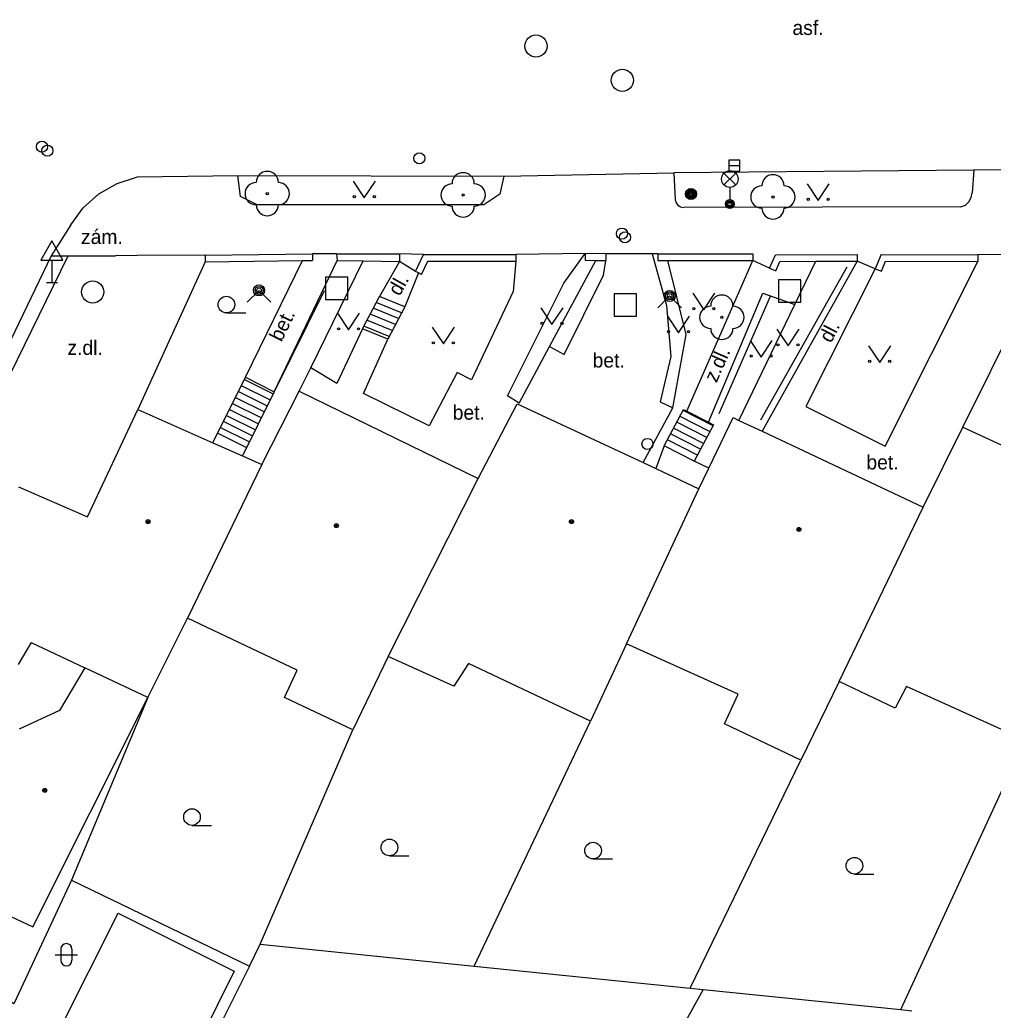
# Model space of a CAD drawing. Extents: x -600309 to -598967, y -1161267 to -1160292.
# Drawn here: x -599981.24 to -599937.41, y -1160664.81 to -1160620.23 of the extents above; entities that cross this region are included whole.
import ezdxf

# ---------------------------------------------------------------- set-up
doc = ezdxf.new("R2010")
doc.units = 0
for name, color, linetype in [('Level 10', 7, 'Continuous'), ('Level 11', 7, 'Continuous'), ('Level 22', 7, 'Continuous'), ('Level 25', 7, 'Continuous'), ('Level 26', 7, 'Continuous'), ('Level 27', 7, 'Continuous'), ('Level 28', 7, 'Continuous'), ('Level 31', 7, 'Continuous'), ('Level 33', 7, 'Continuous'), ('Level 34', 7, 'Continuous'), ('Level 36', 7, 'Continuous'), ('Level 39', 7, 'Continuous'), ('Level 40', 7, 'Continuous'), ('Level 5', 7, 'Continuous'), ('Level 51', 7, 'Continuous'), ('Level 7', 7, 'Continuous'), ('Level 8', 7, 'Continuous')]:
    doc.layers.add(name, color=color, linetype=linetype)

msp = doc.modelspace()

# ---------------------------------------------------------------- linework, layer by layer
at = {"layer": 'Level 10'}
for points in [[(-599959.45, -1160627.26), (-599951.79, -1160627.11)], [(-599938.28, -1160627), (-599951.79, -1160627.11)], [(-599930.96, -1160626.92), (-599938.28, -1160627)], [(-599978.95, -1160629.46), (-599978.39, -1160628.69), (-599977.68, -1160628.06), (-599976.86, -1160627.59), (-599975.95, -1160627.3)], [(-599975.95, -1160627.3), (-599971.43, -1160627.24)], [(-599971.43, -1160627.24), (-599959.45, -1160627.26)], [(-599978.95, -1160629.46), (-599979.83, -1160630.85)], [(-599979.83, -1160630.85), (-599983.85, -1160639.19), (-599988.07, -1160648)]]:
    msp.add_lwpolyline(points, dxfattribs=at)
at = {"layer": 'Level 11'}
for points in [[(-599951.79, -1160627.11), (-599951.73, -1160628.33)], [(-599938.28, -1160627), (-599938.36, -1160628.02)], [(-599959.45, -1160627.26), (-599959.63, -1160628.07), (-599960.35, -1160628.55), (-599970.55, -1160628.55), (-599970.97, -1160628.34), (-599971.3, -1160628.18), (-599971.43, -1160627.24)], [(-599938.86, -1160628.65), (-599938.6599, -1160628.57), (-599938.5, -1160628.42), (-599938.4, -1160628.23), (-599938.36, -1160628.02)], [(-599951.73, -1160628.33), (-599951.69, -1160628.46), (-599951.61, -1160628.57), (-599951.49, -1160628.65), (-599951.36, -1160628.68)], [(-599938.86, -1160628.65), (-599951.36, -1160628.68)], [(-599979.83, -1160630.85), (-599979.06, -1160630.85)], [(-599972.9, -1160631.12), (-599975.93, -1160637.77)], [(-599971.08, -1160636.32), (-599968.51, -1160631.07)], [(-599969.79, -1160636.98), (-599966.96, -1160631.06)], [(-599968.66, -1160636.95), (-599968.14, -1160635.89), (-599965.78, -1160631.08)], [(-599958.91, -1160631.09), (-599959.02, -1160632.46), (-599960.9, -1160636.44), (-599961.55, -1160636.11), (-599962.81, -1160638.5), (-599965.76, -1160637.05), (-599964.67, -1160634.61)], [(-599964.15, -1160631.11), (-599965.05, -1160632.68)], [(-599963.06, -1160630.8), (-599964.15, -1160630.77)], [(-599958.76, -1160637.49), (-599959.28, -1160637.15), (-599956.75, -1160632.09), (-599955.78, -1160630.75)], [(-599957.39, -1160634.94), (-599956.73, -1160635.29), (-599954.96, -1160631.72), (-599954.86, -1160631.07)], [(-599953.18, -1160640.16), (-599951.84, -1160637.69), (-599951.24, -1160634.4), (-599952.06, -1160631.06)], [(-599952.77, -1160630.76), (-599952.12, -1160633.09), (-599951.93, -1160635.39), (-599952.41, -1160637.42), (-599951.84, -1160637.69)], [(-599951.21, -1160637.84), (-599948.23, -1160631.07)], [(-599943.54, -1160631.09), (-599947.82, -1160638.75)], [(-599942.72, -1160631.44), (-599945.85, -1160637.63), (-599942.28, -1160639.42), (-599938.1, -1160631.11)], [(-599963.29, -1160631.62), (-599963.91, -1160633.15)], [(-599965.81, -1160634.14), (-599965.05, -1160632.68)], [(-599963.91, -1160633.15), (-599965.05, -1160632.68)], [(-599950.23, -1160638.34), (-599947.79, -1160632.53), (-599946.34, -1160633.05)], [(-599964.19, -1160633.68), (-599965.33, -1160633.21)], [(-599964.05, -1160633.42), (-599965.19, -1160632.95)], [(-599963.91, -1160633.15), (-599964.67, -1160634.61)], [(-599964.47, -1160634.22), (-599965.61, -1160633.75)], [(-599964.33, -1160633.95), (-599965.47, -1160633.48)], [(-599965.81, -1160634.14), (-599966.97, -1160636.6), (-599968.14, -1160635.89)], [(-599964.67, -1160634.61), (-599965.81, -1160634.14)], [(-599964.61, -1160634.49), (-599965.75, -1160634.02)], [(-599972.55, -1160639.27), (-599971.08, -1160636.32)], [(-599971.13, -1160636.42), (-599969.83, -1160637.06)], [(-599971.08, -1160636.32), (-599969.79, -1160636.98)], [(-599971.27, -1160636.69), (-599969.97, -1160637.33)], [(-599971.53, -1160637.23), (-599970.23, -1160637.87)], [(-599971.4, -1160636.96), (-599970.1, -1160637.6)], [(-599969.79, -1160636.98), (-599971.22, -1160639.86)], [(-599971.8, -1160637.77), (-599970.5, -1160638.41)], [(-599971.66, -1160637.5), (-599970.36, -1160638.14)], [(-599952.22, -1160639.4), (-599951.35, -1160637.77), (-599951.21, -1160637.84), (-599950.23, -1160638.34), (-599950, -1160638.46), (-599950.87, -1160640.09)], [(-599950.02, -1160638.5), (-599951.37, -1160637.81)], [(-599971.93, -1160638.04), (-599970.63, -1160638.68)], [(-599950.16, -1160638.77), (-599951.51, -1160638.08)], [(-599972.2, -1160638.58), (-599970.9, -1160639.22)], [(-599972.06, -1160638.31), (-599970.76, -1160638.95)], [(-599950.45, -1160639.3), (-599951.8, -1160638.61)], [(-599950.3, -1160639.03), (-599951.65, -1160638.34)], [(-599972.33, -1160638.84), (-599971.03, -1160639.48)], [(-599950.73, -1160639.82), (-599952.08, -1160639.13)], [(-599950.59, -1160639.56), (-599951.94, -1160638.87)], [(-599952.22, -1160639.4), (-599952.61, -1160640.43)], [(-599950.87, -1160640.09), (-599952.22, -1160639.4)], [(-599950.21, -1160640.41), (-599950.87, -1160640.09)]]:
    msp.add_lwpolyline(points, dxfattribs=at)
at = {"layer": 'Level 22'}
for centre in [(-599970.1, -1160628.05), (-599961.28, -1160628.11), (-599947.33, -1160628.2), (-599949.63, -1160633.62)]:
    msp.add_circle(centre, 0.05, dxfattribs=at)
for centre, start, end in [((-599970.1, -1160627.55), 0, 180), ((-599961.28, -1160627.61), 0, 180), ((-599970.6, -1160628.05), 90, 270), ((-599969.6, -1160628.05), 270, 90), ((-599947.33, -1160627.7), 0, 180), ((-599961.78, -1160628.11), 90, 270), ((-599960.78, -1160628.11), 270, 90), ((-599947.83, -1160628.2), 90, 270), ((-599946.83, -1160628.2), 270, 90), ((-599970.1, -1160628.55), 180, 0), ((-599961.28, -1160628.61), 180, 0), ((-599947.33, -1160628.7), 180, 0), ((-599949.63, -1160633.12), 0, 180), ((-599950.13, -1160633.62), 90, 270), ((-599949.13, -1160633.62), 270, 90), ((-599949.63, -1160634.12), 180, 0)]:
    msp.add_arc(centre, 0.5, start, end, dxfattribs=at)
at = {"layer": 'Level 25'}
for radius in [0.25, 0.2, 0.15, 0.1, 0.05]:
    msp.add_circle((-599951.02, -1160628.07), radius, dxfattribs=at)
at = {"layer": 'Level 26'}
for points in [[(-599967.48, -1160632.82), (-599966.48, -1160632.82), (-599966.48, -1160631.82), (-599967.48, -1160631.82)], [(-599947.08, -1160632.94), (-599946.08, -1160632.94), (-599946.08, -1160631.94), (-599947.08, -1160631.94)], [(-599954.48, -1160633.57), (-599953.48, -1160633.57), (-599953.48, -1160632.57), (-599954.48, -1160632.57)]]:
    msp.add_lwpolyline(points, close=True, dxfattribs=at)
at = {"layer": 'Level 27'}
msp.add_line((-599949.32, -1160626.79), (-599948.82, -1160626.79), dxfattribs=at)
msp.add_lwpolyline([(-599949.32, -1160627.04), (-599948.82, -1160627.04), (-599948.82, -1160626.54), (-599949.32, -1160626.54)], close=True, dxfattribs=at)
for centre in [(-599958, -1160621.41), (-599954.11, -1160622.95), (-599977.96, -1160632.48)]:
    msp.add_circle(centre, 0.5, dxfattribs=at)
at = {"layer": 'Level 28'}
for centre in [(-599980.25, -1160625.94), (-599980, -1160626.12), (-599963.25, -1160626.46), (-599954.13, -1160629.85), (-599953.99, -1160630.02)]:
    msp.add_circle(centre, 0.25, dxfattribs=at)
at = {"layer": 'Level 31'}
for points in [[(-599971, -1160632.94), (-599970.47, -1160632.41), (-599969.94, -1160632.94)], [(-599952.51, -1160633.19), (-599951.98, -1160632.66), (-599951.45, -1160633.19)]]:
    msp.add_lwpolyline(points, dxfattribs=at)
for centre, radius in [((-599970.47, -1160632.41), 0.25), ((-599970.47, -1160632.41), 0.18), ((-599970.47, -1160632.41), 0.11), ((-599951.98, -1160632.66), 0.25), ((-599951.98, -1160632.66), 0.18), ((-599951.98, -1160632.66), 0.11), ((-599952.98, -1160639.32), 0.25)]:
    msp.add_circle(centre, radius, dxfattribs=at)
at = {"layer": 'Level 33'}
for p, q in [((-599949.535, -1160627.66), (-599949.005, -1160627.13)), ((-599949.535, -1160627.13), (-599949.005, -1160627.66)), ((-599949.27, -1160627.77), (-599949.27, -1160628.52))]:
    msp.add_line(p, q, dxfattribs=at)
for centre, radius in [((-599949.27, -1160627.395), 0.375), ((-599949.27, -1160628.52), 0.2), ((-599949.27, -1160628.52), 0.1445), ((-599949.27, -1160628.52), 0.0876)]:
    msp.add_circle(centre, radius, dxfattribs=at)
at = {"layer": 'Level 34'}
for p, q in [((-599979.8, -1160631.042), (-599979.8, -1160632.06)), ((-599980.05, -1160632.06), (-599979.55, -1160632.06))]:
    msp.add_line(p, q, dxfattribs=at)
msp.add_lwpolyline([(-599980.3, -1160631.042), (-599979.3, -1160631.042), (-599979.8, -1160630.176)], close=True, dxfattribs=at)
at = {"layer": 'Level 36'}
for p, q in [((-599971.94, -1160633.425), (-599971.065, -1160633.425)), ((-599973.49, -1160656.495), (-599972.615, -1160656.495)), ((-599964.6, -1160657.865), (-599963.725, -1160657.865)), ((-599955.43, -1160658.005), (-599954.555, -1160658.005)), ((-599943.6599, -1160658.685), (-599942.7849, -1160658.685)), ((-599979.646, -1160662.316), (-599978.646, -1160662.316)), ((-599979.396, -1160662.066), (-599979.396, -1160662.566)), ((-599978.896, -1160662.066), (-599978.896, -1160662.566))]:
    msp.add_line(p, q, dxfattribs=at)
for points in [[(-599966.23, -1160627.49), (-599965.73, -1160628.24), (-599965.23, -1160627.49)], [(-599945.79, -1160627.61), (-599945.29, -1160628.36), (-599944.79, -1160627.61)], [(-599950.94, -1160632.53), (-599950.44, -1160633.28), (-599949.94, -1160632.53)], [(-599957.78, -1160633.19), (-599957.28, -1160633.94), (-599956.78, -1160633.19)], [(-599966.94, -1160633.44), (-599966.44, -1160634.19), (-599965.94, -1160633.44)], [(-599952.08, -1160633.57), (-599951.58, -1160634.32), (-599951.08, -1160633.57)], [(-599962.67, -1160634.07), (-599962.17, -1160634.82), (-599961.67, -1160634.07)], [(-599947.15, -1160634.16), (-599946.65, -1160634.91), (-599946.15, -1160634.16)], [(-599948.36, -1160634.66), (-599947.86, -1160635.41), (-599947.36, -1160634.66)], [(-599943.02, -1160634.9), (-599942.52, -1160635.65), (-599942.02, -1160634.9)]]:
    msp.add_lwpolyline(points, dxfattribs=at)
for centre, radius in [((-599966.1802, -1160628.1898), 0.05), ((-599965.2808, -1160628.1898), 0.05), ((-599945.7402, -1160628.3098), 0.05), ((-599944.8408, -1160628.3098), 0.05), ((-599971.9401, -1160633.0499), 0.375), ((-599950.8902, -1160633.2298), 0.05), ((-599949.9908, -1160633.2298), 0.05), ((-599966.8902, -1160634.1398), 0.05), ((-599965.9908, -1160634.1398), 0.05), ((-599957.7302, -1160633.8898), 0.05), ((-599956.8308, -1160633.8898), 0.05), ((-599952.0302, -1160634.2698), 0.05), ((-599951.1308, -1160634.2698), 0.05), ((-599962.6202, -1160634.7698), 0.05), ((-599961.7208, -1160634.7698), 0.05), ((-599947.1002, -1160634.8598), 0.05), ((-599946.2008, -1160634.8598), 0.05), ((-599948.3102, -1160635.3598), 0.05), ((-599947.4108, -1160635.3598), 0.05), ((-599942.9702, -1160635.5998), 0.05), ((-599942.0708, -1160635.5998), 0.05), ((-599973.4901, -1160656.1199), 0.375), ((-599964.6001, -1160657.4899), 0.375), ((-599955.4301, -1160657.6299), 0.375), ((-599943.66, -1160658.3099), 0.375)]:
    msp.add_circle(centre, radius, dxfattribs=at)
for centre, start, end in [((-599979.1457, -1160662.0663), 0, 180), ((-599979.1457, -1160662.5663), 180, 0)]:
    msp.add_arc(centre, 0.25, start, end, dxfattribs=at)
at = {"layer": 'Level 39'}
for centre, radius in [((-599975.4699, -1160642.82), 0.09), ((-599956.4, -1160642.82), 0.09), ((-599975.4699, -1160642.82), 0.0398), ((-599966.99, -1160643), 0.09), ((-599966.99, -1160643), 0.0398), ((-599956.4, -1160642.82), 0.0398), ((-599946.1599, -1160643.17), 0.09), ((-599946.1599, -1160643.17), 0.0398), ((-599980.12, -1160654.92), 0.09), ((-599980.12, -1160654.92), 0.0398)]:
    msp.add_circle(centre, radius, dxfattribs=at)
at = {"layer": 'Level 5'}
for points in [[(-599970.34, -1160640.25), (-599968.6599, -1160636.95)], [(-599968.6599, -1160636.95), (-599960.6, -1160640.87)], [(-599978.19, -1160642.6), (-599975.93, -1160637.77)], [(-599975.93, -1160637.77), (-599972.55, -1160639.27), (-599971.22, -1160639.86), (-599970.34, -1160640.25)], [(-599960.6, -1160640.87), (-599958.84, -1160637.52)], [(-599958.84, -1160637.52), (-599953.18, -1160640.16), (-599952.61, -1160640.43), (-599950.6599, -1160641.34)], [(-599950.6599, -1160641.34), (-599950.21, -1160640.41), (-599949.12, -1160638.13)], [(-599949.12, -1160638.13), (-599948.86, -1160638.26), (-599947.82, -1160638.75), (-599940.56, -1160642.17)], [(-599940.56, -1160642.17), (-599938.77, -1160638.56)], [(-599938.77, -1160638.56), (-599930.8, -1160642.25)], [(-599970.34, -1160640.25), (-599973.69, -1160647.1599)], [(-599964.65, -1160648.89), (-599960.6, -1160640.87)], [(-599981.3, -1160641.25), (-599978.19, -1160642.6)], [(-599953.93, -1160648.32), (-599950.6599, -1160641.34)], [(-599944.35, -1160650.02), (-599940.56, -1160642.17)], [(-599975.48, -1160650.73), (-599973.69, -1160647.1599)], [(-599968.75, -1160649.51), (-599973.69, -1160647.1599)], [(-599980.74, -1160648.26), (-599981.32, -1160649.25)], [(-599980.74, -1160648.26), (-599978.32, -1160649.4)], [(-599953.93, -1160648.32), (-599955.55, -1160651.81)], [(-599948.89, -1160650.59), (-599953.93, -1160648.32)], [(-599964.65, -1160648.89), (-599966.25, -1160652.19)], [(-599961.7, -1160650.2199), (-599964.65, -1160648.89)], [(-599978.32, -1160649.4), (-599979.45, -1160651.32)], [(-599975.48, -1160650.73), (-599978.32, -1160649.4)], [(-599961.04, -1160649.21), (-599961.7, -1160650.2199)], [(-599955.55, -1160651.81), (-599961.04, -1160649.21)], [(-599969.33, -1160650.74), (-599968.75, -1160649.51)], [(-599944.35, -1160650.02), (-599946.07, -1160653.56)], [(-599941.82, -1160651.21), (-599944.35, -1160650.02)], [(-599941.32, -1160650.24), (-599941.82, -1160651.21)], [(-599935.9699, -1160652.6599), (-599941.32, -1160650.24)], [(-599980.6599, -1160661.06), (-599975.48, -1160650.73)], [(-599966.25, -1160652.19), (-599969.33, -1160650.74)], [(-599949.51, -1160651.92), (-599948.89, -1160650.59)], [(-599979.45, -1160651.32), (-599981.27, -1160652.1599)], [(-599946.07, -1160653.56), (-599949.51, -1160651.92)], [(-599985.01, -1160659.02), (-599980.6599, -1160661.06)], [(-599979.83, -1160666.45), (-599979.469, -1160665.7305), (-599976.82, -1160660.45)], [(-599976.82, -1160660.45), (-599971.59, -1160663.06)], [(-599971.59, -1160663.06), (-599974.61, -1160669.15)]]:
    msp.add_lwpolyline(points, dxfattribs=at)
at = {"layer": 'Level 51'}
for points in [[(-599975.48, -1160650.73), (-599978.92, -1160658.96)], [(-599960.78, -1160662.83), (-599955.55, -1160651.81)], [(-599970.42, -1160661.84), (-599966.25, -1160652.19)], [(-599941.57, -1160664.79), (-599935.9699, -1160652.6599)], [(-599951.06, -1160663.82), (-599946.07, -1160653.56)], [(-599978.92, -1160658.96), (-599970.9, -1160662.83)], [(-599970.9, -1160662.83), (-599970.42, -1160661.84)], [(-599970.42, -1160661.84), (-599960.78, -1160662.83)], [(-599970.9, -1160662.83), (-599974.17, -1160669.38)], [(-599960.78, -1160662.83), (-599951.06, -1160663.82)], [(-599950.4699, -1160663.88), (-599954.11, -1160670.45)], [(-599951.06, -1160663.82), (-599950.4699, -1160663.88)], [(-599950.4699, -1160663.88), (-599941.57, -1160664.79)], [(-599941.57, -1160664.79), (-599941.07, -1160664.84)]]:
    msp.add_lwpolyline(points, dxfattribs=at)
at = {"layer": 'Level 7'}
for points in [[(-599987.92, -1160657.27), (-599988.46, -1160654.9699), (-599988.51, -1160652.08), (-599988.23, -1160650.35), (-599987.52, -1160648.14), (-599983.33, -1160639.54), (-599979.06, -1160630.85)], [(-599979.06, -1160630.85), (-599978.69, -1160630.86), (-599976.94, -1160630.85)], [(-599972.9, -1160630.82), (-599968.06, -1160630.76)], [(-599972.9, -1160630.82), (-599972.9, -1160631.12)], [(-599972.9, -1160631.12), (-599968.51, -1160631.07), (-599968.06, -1160631.06)], [(-599968.06, -1160630.76), (-599968.06, -1160631.06)], [(-599966.99, -1160630.76), (-599964.15, -1160630.77)], [(-599966.99, -1160630.76), (-599966.96, -1160631.06)], [(-599966.96, -1160631.06), (-599965.78, -1160631.08), (-599964.15, -1160631.11)], [(-599964.15, -1160630.77), (-599964.15, -1160631.11)], [(-599963.15, -1160631.69), (-599963.29, -1160631.62), (-599963.42, -1160631.56), (-599963.06, -1160630.8)], [(-599963.15, -1160631.69), (-599962.87, -1160631.1), (-599958.91, -1160631.09)], [(-599963.06, -1160630.8), (-599958.91, -1160630.79)], [(-599958.91, -1160630.79), (-599958.91, -1160631.09)], [(-599958.76, -1160637.49), (-599957.39, -1160634.94), (-599955.3, -1160631.06)], [(-599955.78, -1160630.75), (-599955.79, -1160631.05)], [(-599955.79, -1160631.05), (-599955.3, -1160631.06), (-599954.86, -1160631.07)], [(-599954.85, -1160630.77), (-599955.78, -1160630.75)], [(-599954.85, -1160630.77), (-599954.86, -1160631.07)], [(-599952.51, -1160630.76), (-599952.25, -1160630.76), (-599948.23, -1160630.77)], [(-599952.51, -1160630.76), (-599952.51, -1160631.06)], [(-599952.51, -1160631.06), (-599952.06, -1160631.06), (-599948.23, -1160631.07)], [(-599948.86, -1160638.26), (-599946.34, -1160633.05), (-599945.4, -1160631.1)], [(-599948.23, -1160630.77), (-599948.23, -1160631.07)], [(-599947.48, -1160631.41), (-599947.22, -1160630.81)], [(-599947.22, -1160630.81), (-599943.54, -1160630.79)], [(-599947.2, -1160631.53), (-599947.02, -1160631.11), (-599945.4, -1160631.1), (-599943.54, -1160631.09)], [(-599943.54, -1160630.79), (-599943.54, -1160631.09)], [(-599942.46, -1160630.79), (-599942.72, -1160631.44)], [(-599942.46, -1160630.79), (-599938.1, -1160630.81)], [(-599942.44, -1160631.55), (-599942.26, -1160631.09), (-599938.1, -1160631.11)], [(-599938.77, -1160638.56), (-599936.24, -1160633.46), (-599935.07, -1160631.12)], [(-599938.1, -1160630.81), (-599938.1, -1160631.11)], [(-599947.88, -1160638.24), (-599943.98, -1160631.35)], [(-599947.48, -1160631.41), (-599947.2, -1160631.53)], [(-599942.72, -1160631.44), (-599942.44, -1160631.55)], [(-599967.54, -1160632.43), (-599969.79, -1160636.98)], [(-599947.46, -1160632.68), (-599949.76, -1160637.96)], [(-599978.92, -1160658.96), (-599981.52, -1160664.53), (-599983.56, -1160663.27), (-599984.98, -1160662.02), (-599986.2, -1160660.58), (-599987.2, -1160658.9699), (-599987.92, -1160657.27)]]:
    msp.add_lwpolyline(points, dxfattribs=at)
at = {"layer": 'Level 8'}
for points in [[(-599972.9, -1160630.82), (-599975.96, -1160630.84), (-599976.94, -1160630.85)], [(-599966.99, -1160630.76), (-599968.06, -1160630.76)], [(-599963.42, -1160631.56), (-599964.15, -1160631.11)], [(-599955.78, -1160630.75), (-599958.91, -1160630.79)], [(-599952.51, -1160630.76), (-599952.77, -1160630.76), (-599954.85, -1160630.77)], [(-599947.48, -1160631.41), (-599948.23, -1160631.07)], [(-599942.72, -1160631.44), (-599943.54, -1160631.09)], [(-599935.58, -1160630.8), (-599938.1, -1160630.81)]]:
    msp.add_lwpolyline(points, dxfattribs=at)

# ---------------------------------------------------------------- texts
at = {"layer": 'Level 40'}
for s, p in [('asf.', (-599946.45, -1160620.91)), ('zám.', (-599978.49, -1160630.32)), ('z.dl.', (-599979.1, -1160635.31)), ('bet.', (-599955.45, -1160635.88)), ('bet.', (-599961.75, -1160638.23)), ('bet.', (-599943.12, -1160640.47))]:
    msp.add_text(s, height=0.65, dxfattribs=at).set_placement(p)
for s, rotation, p in [('dl.', 60.8368, (-599964.14, -1160632.7)), ('bet.', 63.96833, (-599969.46, -1160634.76)), ('dl.', 62.82973, (-599944.71, -1160634.81)), ('z.dl.', 66.24512, (-599949.87, -1160636.6))]:
    msp.add_text(s, height=0.65, rotation=rotation, dxfattribs=at).set_placement(p)

doc.saveas('drawing.dxf')
